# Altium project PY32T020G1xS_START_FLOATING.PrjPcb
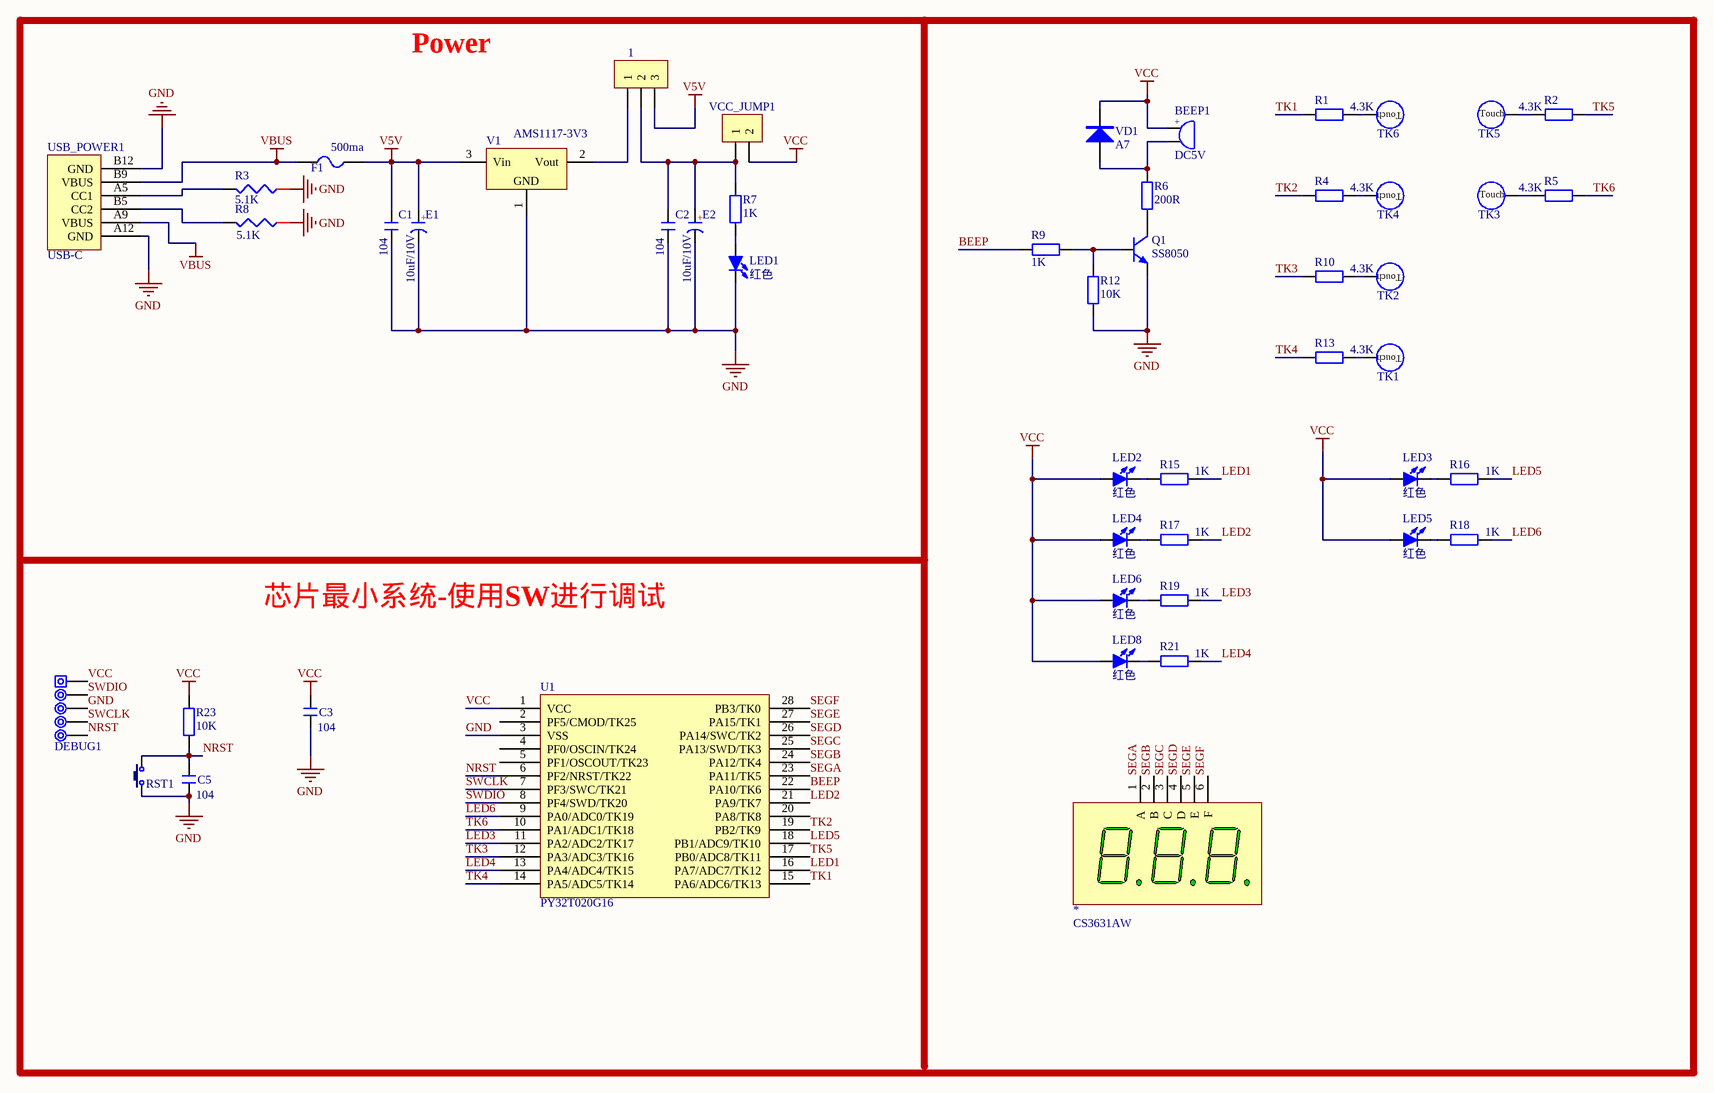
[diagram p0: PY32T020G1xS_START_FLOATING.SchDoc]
1 sheet, 50 parts. Net scope: global (net labels, ports and power ports of the same name join across sheets).
Board file: PY32T020G1xS_START_FLOATING.PcbDoc

## Sheet PY32T020G1xS_START_FLOATING.SchDoc
size A3

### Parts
1  HDR-1X3  [HDR2.54-LI-3P]  (value not drawn)
*  CS3631AW
BEEP1  DC5V  [BEEP 5x9x5.5]
C1  104  [C 0603_L]
C2  104  [C 0603_L]
C3  104  [C 0603_L]
C5  104  [C 0603_L]
DEBUG1  ISP  [ISP_DIP_2.54_5P]  (value not drawn)
E1  10uF/10V  [C 0805_L]
E2  10uF/10V  [C 0805_L]
F1  500ma  [FU 0805]
LED1  红色  [LED 0805R]
LED2  红色  [LED 0805G]
LED3  红色  [LED 0805G]
LED4  红色  [LED 0805G]
LED5  红色  [LED 0805G]
LED6  红色  [LED 0805G]
LED8  红色  [LED 0805G]
Q1  SS8050  [SOT23-3L]
R1  4.3K  [R 0603_L]
R2  4.3K  [R 0603_L]
R3  5.1K  [R 0603_L]
R4  4.3K  [R 0603_L]
R5  4.3K  [R 0603_L]
R6  200R  [R 0603_L]
R7  1K  [R 0603_L]
R8  5.1K  [R 0603_L]
R9  1K  [R 0603_L]
R10  4.3K  [R 0603_L]
R12  10K  [R 0603_L]
R13  4.3K  [R 0603_L]
R15  1K  [R 0603_L]
R16  1K  [R 0603_L]
R17  1K  [R 0603_L]
R18  1K  [R 0603_L]
R19  1K  [R 0603_L]
R21  1K  [R 0603_L]
R23  10K  [R 0603_L]
RST1  6x6x5  [TSW SMD-3*6*5]  (value not drawn)
TK1  Touch 10X10mm  [Touch-10X10mm]  (value not drawn)
TK2  Touch 10X10mm  [Touch-10X10mm]  (value not drawn)
TK3  Touch 10X10mm  [Touch-10X10mm]  (value not drawn)
TK4  Touch 10X10mm  [Touch-10X10mm]  (value not drawn)
TK5  Touch 10X10mm  [Touch-10X10mm]  (value not drawn)
TK6  Touch 10X10mm  [Touch-10X10mm]  (value not drawn)
U1  PY32T020G16  [SOP28_L]
USB_POWER1  USB-C  [USB-C/S_C]
V1  AMS1117-3V3  [SOT223_N]
VCC_JUMP1  HDR-1X2  [HDR2.54-LI-2P]  (value not drawn)
VD1  A7  [SOD-123]

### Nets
GND: C1.1 C2.1 C3.1 C5.1 DEBUG1.3 E1.2(K) E2.2(K) LED1.2(K) Q1.2(B) R3.1 R8.1 R12.1 RST1.1 U1.3(VSS) USB_POWER1.A12(GND) USB_POWER1.B12(GND) V1.1(GND)
V5V: 1.3 C1.2 E1.1(A) F1.2 V1.3(Vin)
VBUS: F1.1 USB_POWER1.A9(VBUS) USB_POWER1.B9(VBUS)
VCC: BEEP1.1 C3.2 DEBUG1.1 LED2.1(A) LED3.1(A) LED4.1(A) LED5.1(A) LED6.1(A) LED8.1(A) R23.2 U1.1(VCC) VCC_JUMP1.2 VD1.K
BEEP: R9.2 U1.22(PA10/TK6)
LED1: R15.2 U1.16(PA7/ADC7/TK12)
LED2: R17.2 U1.21(PA9/TK7)
LED3: R19.2 U1.11(PA2/ADC2/TK17)
LED4: R21.2 U1.13(PA4/ADC4/TK15)
LED5: R16.2 U1.18(PB1/ADC9/TK10)
LED6: R18.2 U1.9(PA0/ADC0/TK19)
NRST: C5.2 DEBUG1.5 R23.1 RST1.2 U1.6(PF2/NRST/TK22)
SEGA: *.1(A) U1.23(PA11/TK5)
SEGB: *.2(B) U1.24(PA12/TK4)
SEGC: *.3(C) U1.25(PA13/SWD/TK3)
SEGD: *.4(D) U1.26(PA14/SWC/TK2)
SEGE: *.5(E) U1.27(PA15/TK1)
SEGF: *.6(F) U1.28(PB3/TK0)
SWCLK: DEBUG1.4 U1.7(PF3/SWC/TK21)
SWDIO: DEBUG1.2 U1.8(PF4/SWD/TK20)
TK1: R1.1 U1.15(PA6/ADC6/TK13)
TK2: R4.1 U1.19(PB2/TK9)
TK3: R10.1 U1.12(PA3/ADC3/TK16)
TK4: R13.1 U1.14(PA5/ADC5/TK14)
TK5: R2.1 U1.17(PB0/ADC8/TK11)
TK6: R5.1 U1.10(PA1/ADC1/TK18)
Net1_1: 1.1 V1.2(Vout)
Net1_2: 1.2 C2.2 E2.1(A) R7.2 VCC_JUMP1.1
NetBEEP1_2: BEEP1.2 R6.2 VD1.A
NetLED1_1: LED1.1(A) R7.1
NetLED2_2: LED2.2(K) R15.1
NetLED3_2: LED3.2(K) R16.1
NetLED4_2: LED4.2(K) R17.1
NetLED5_2: LED5.2(K) R18.1
NetLED6_2: LED6.2(K) R19.1
NetLED8_2: LED8.2(K) R21.1
NetQ1_1: Q1.1(E) R9.1 R12.2
NetQ1_3: Q1.3(C) R6.1
NetR1_2: R1.2 TK6.Touch
NetR2_2: R2.2 TK5.Touch
NetR3_2: R3.2 USB_POWER1.A5(CC1)
NetR4_2: R4.2 TK4.Touch
NetR5_2: R5.2 TK3.Touch
NetR8_2: R8.2 USB_POWER1.B5(CC2)
NetR10_2: R10.2 TK2.Touch
NetR13_2: R13.2 TK1.Touch

Not connected (* = marked no-connect by the designer): U1 2(PF5/CMOD/TK25) 4(PF0/OSCIN/TK24) 5(PF1/OSCOUT/TK23) 20(PA8/TK8)

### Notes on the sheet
- Power
- 芯片最小系统-使用SW进行调试

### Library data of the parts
1 = Header 3: 3P接插件; 版权归属: 源创客
BEEP1 = BEEP: 蜂鸣器; 版权归属: 源创客
C1-C3 C5 = C: 无极性贴片电容; 版权归属: 源创客; 材质: X7R
DEBUG1 = ISP_5Pin: 程序下载端口; 版权归属: 源创客
E1 E2 = C-CM: 贴片电解电容; 版权归属: 源创客
F1 = FU: 贴片保险丝; 版权归属: 源创客
LED1-LED6 LED8 = LED-SMD: 贴片LED; 版权归属: 源创客
Q1 = 8050-DIP: 高频放大-NPN型; 版权归属: 源创客; 属性: 40V 1.5A 1W 100MHZ
R1 R2 R4-R7 R9 R10 R12 R13 R15-R19 R21 R23 = R: 贴片电阻; 版权归属: 源创客
R3 R8 = R
RST1 = TSW DIP-2Pin-6x6: 2脚直插6x6轻触开关; BOM名称: 2脚轻触开关; 版权归属: 源创客
TK1-TK6 = Touch-1P: 触控焊盘; 版权归属: 源创客
USB_POWER1 = USB-C_6P/S: USB-C_6P型母接口; BOM名称: USB-C型母接口; 版权归属: 源创客
V1 = AMS1117: 三端稳压芯片; BOM名称: 稳压芯片; 版权归属: 源创客
VCC_JUMP1 = Header 2: 2P接插件; 版权归属: 源创客
VD1 = DIODE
